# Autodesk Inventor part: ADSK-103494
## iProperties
Shininess: 0.0
Created: 2000-10
Part Number: ADSK-103494
Document SubType Name: Modeling
Designer: Administrator
Stock Number: ADSK-103494
Density: 1 g/cm^3
Density: 0.0
Volumn: 0.0
Area: 0.0
PropertySet Name: Model Information
Control State: 0
Master: False
Checked Out: False
Author: Administrator
